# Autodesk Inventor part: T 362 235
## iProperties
Company: Mayer & Müller AG Schaltgeräte
Created: 2006-08
Part Number: T 362 235
Material: Durethan BKV30H
Document SubType Name: Modeling
Designer: I.Baliuc
Description: Isolator
Density: 0.94 g/cm^3
Mass: 29.8914 g
Surface Area: 201.754 cm^2
Volume: 31.7994 cm^3
Author: T.Messerschmitt
Keywords: 213549
Revision Number: 362235
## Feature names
1. Extrusion3
2. Extrusion4
3. Bohrung1 [Hole]
4. Spiegeln1 [Mirror]
5. Bohrung2 [Hole]
